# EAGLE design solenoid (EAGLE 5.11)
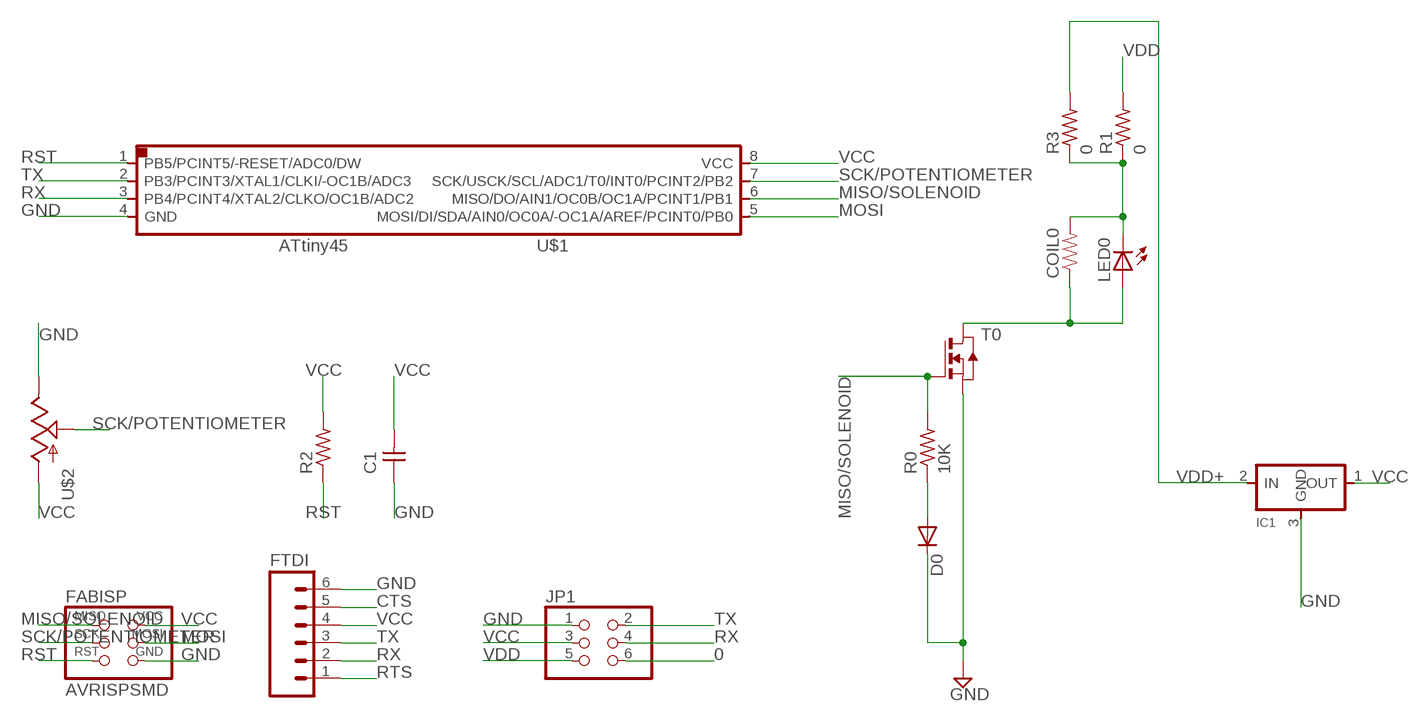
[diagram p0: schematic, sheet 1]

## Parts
C1  UNPOLARIZED_CAPACITOR1206  [1206]
COIL0  RESISTOR1206  [1206]
D0  DIODESOD123  [SOD123]
FABISP  AVRISPSMD  [2X03SMD]
FTDI  M06SMD  [1X06-SMD]
IC1  REGULATORSOT23  [SOT23]
JP1  PINHD-2X3-SMD  [2X03SMD]
LED0  LED1206  [1206]
R0  10K  RESISTOR1206  [1206]
R1  0  RESISTOR1206  [1206]
R2  RESISTOR1206  [1206]
R3  0  RESISTOR1206  [1206]
T0  NMOSFETSOT23  [SOT-23]
U$1  ATTINY45SI  [SOIC8]
U$2  POT  [ALPS_POT]

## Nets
0: JP1.6
CO0: COIL0.1 LED0.1(A) T0.1(D)
CTS: FTDI.5
GND: C1.1 D0.CATHODE(C) FABISP.6(GND) FTDI.6 IC1.3(GND) JP1.1 T0.2(S) U$1.4(GND) U$2.P$1(E)
MISO/SOLENOID: FABISP.1(MISO) R0.2 T0.3(G) U$1.6(MISO/DO/AIN1/OC0B/OC1A/PCINT1/PB1)
MOSI: FABISP.4(MOSI) U$1.5(MOSI/DI/SDA/AIN0/OC0A/-OC1A/AREF/PCINT0/PB0)
N$1: COIL0.2 LED0.2(C) R1.1 R3.1
R0: D0.ANODE(A) R0.1
RST: FABISP.5(RST) R2.1 U$1.1(PB5/PCINT5/-RESET/ADC0/DW)
RTS: FTDI.1
RX: FTDI.2 JP1.4 U$1.3(PB4/PCINT4/XTAL2/CLKO/OC1B/ADC2)
SCK/POTENTIOMETER: FABISP.3(SCK) U$1.7(SCK/USCK/SCL/ADC1/T0/INT0/PCINT2/PB2) U$2.P$2(S)
TX: FTDI.3 JP1.2 U$1.2(PB3/PCINT3/XTAL1/CLKI/-OC1B/ADC3)
VCC: C1.2 FABISP.2(VCC) FTDI.4 IC1.1(OUT) JP1.3 R2.2 U$1.8(VCC) U$2.P$3(A)
VDD: JP1.5 R1.2
VDD+: IC1.2(IN) R3.2

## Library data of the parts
C1 = ng:UNPOLARIZED_CAPACITOR: unpolarized_capacitor
COIL0 = SparkFun:RESISTOR: Resistor
D0 = ng:DIODE: DIODE
FABISP = fab:AVRISP
FTDI = SparkFun:M06: Header 6 Standard 6-pin 0.1" header. Use with straight break away headers (SKU : PRT-00116), right angle break away headers (PRT-00553), swiss pins (PRT-00743), machine pins (PRT-00117), and female headers (PRT-00115). Molex polarized connector foot print use with SKU : PRT-08094 with associated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
IC1 = ng:REGULATOR
JP1 = fab:PINHD-2X3-SMD: PIN HEADER
LED0 = ng:LED
R0 R1-R3 = ng:RESISTOR
T0 = ng:NMOSFET: MOS FET
U$1 = fab:ATTINY45
U$2 = SparkFun:POT

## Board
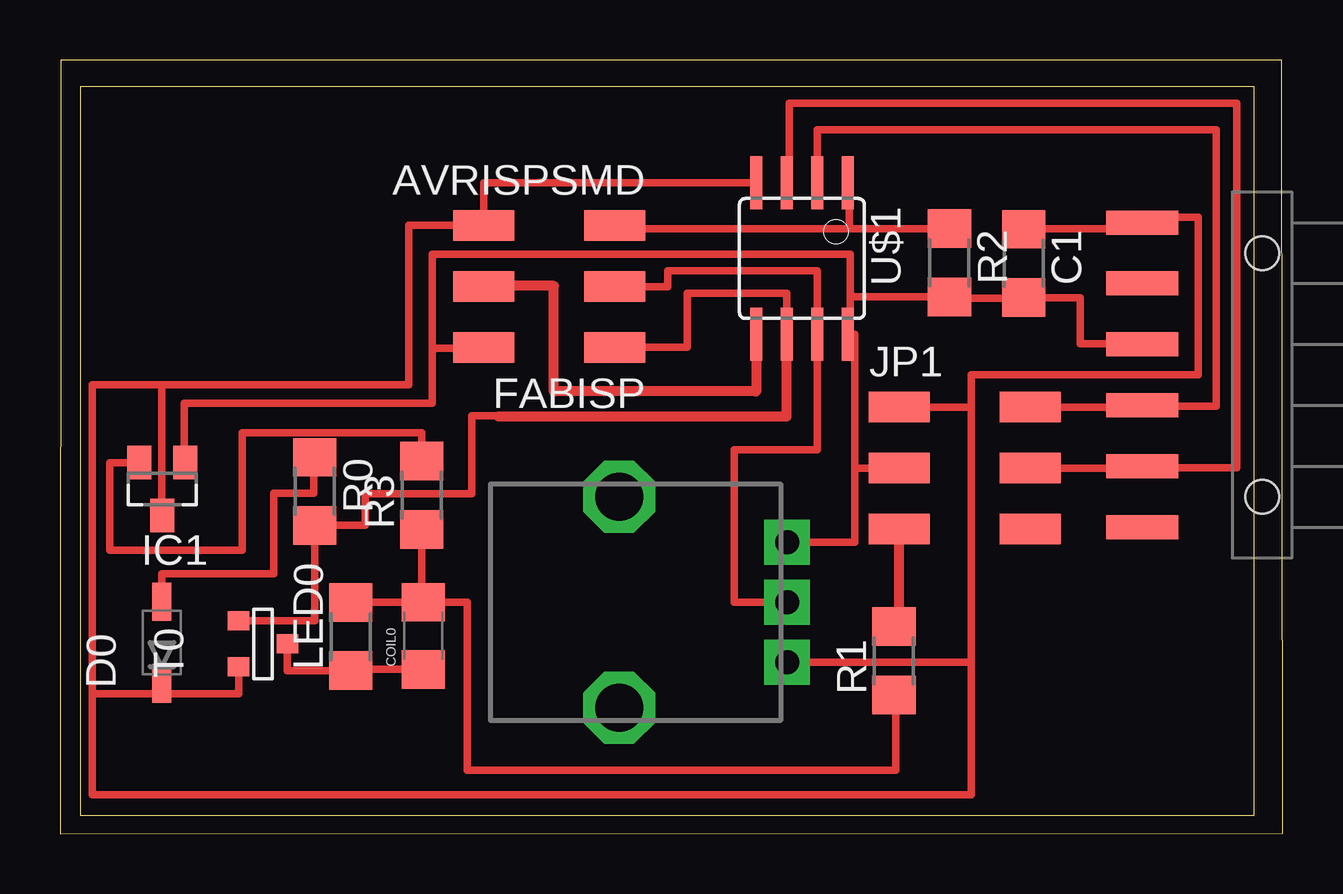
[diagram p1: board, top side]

Size 50.95 x 32.25 mm. Coordinates in mm from the lower left corner, seen from the top.
Outline: 0,0 50.95,0.03 50.9,32.25 0.03,32.25 0,0
Copper layers (1*16): Top 0.035mm / dielectric 1.5mm / Bottom 0.035mm
Design rules "default": minimum track width 10mil, minimum drill 24mil, track to track 8mil, track to pad 8mil, pad to pad 8mil, via to via 8mil, smd to smd 8mil, copper to edge 40mil, drill to drill 8mil, minimum pad ring 10mil, minimum via ring 8mil, stop-mask expansion 4mil, vias tented up to drill 0mil, thermal gap 10mil
Milling: area 0.8,0.8 to 49.8,31.1

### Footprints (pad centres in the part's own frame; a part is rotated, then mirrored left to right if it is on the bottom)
1206 = smd 1.6 x 1.803: 1 -1.422,0; 2 1.422,0
1206' = smd 1.6 x 1.8: 1 -1.4,0; 2 1.4,0
SOD123 = smd 1.6 x 0.8: ANODE 1.7,0; CATHODE -1.7,0
2X03SMD = smd 2.54 x 1.27: 1 -2.54,2.54; 2 2.92,2.54; 3 -2.54,0; 4 2.92,0; 5 -2.54,-2.54; 6 2.92,-2.54
1X06-SMD = smd 1 x 3: 1 -6.35,5; 2 -3.81,5; 3 -1.27,5; 4 1.27,5; 5 3.81,5; 6 6.35,5 | hole 1.4: -5.08,0; 5.08,0
SOT23 = smd 1 x 1.4: 1 -0.95,-1.1; 2 0.95,-1.1; 3 0,1.1
SOT-23 = smd 0.787 x 0.889: 1 0.025,-1.016; 2 -0.94,1.016; 3 0.991,1.016
SOIC8 = smd 0.5 x 2.2: 1 -1.905,-3.154; 2 -0.645,-3.154; 3 0.625,-3.154; 4 1.895,-3.154; 5 1.905,3.154; 6 0.635,3.154; 7 -0.635,3.154; 8 -1.905,3.154
ALPS_POT = drill 1 pad 1.88 square: P$1 7,-2.5; P$2 7,0; P$3 7,2.5 | drill 2 octagon: P$4 0,-4.4; P$5 0,4.4

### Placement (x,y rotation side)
C1  40.16,23.77 270 top
COIL0  [1206']  15.14,8.26 90 top
D0  4.24,7.98 90 top
FABISP  20.57,22.81 180 top
FTDI  50.09,19.13 90 top
IC1  4.26,14.37 180 top
JP1  37.52,15.24 0 top
LED0  12.12,8.23 90 top
R0  10.62,14.27 270 top
R1  34.75,7.21 90 top
R2  37.06,23.8 270 top
R3  15.07,14.11 90 top
T0  8.46,7.9 90 top
U$1  30.91,23.98 180 top
U$2  23.29,9.65 0 top

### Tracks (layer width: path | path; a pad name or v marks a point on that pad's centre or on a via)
CO0
  Top 0.305: COIL0.1 12.12,6.86 LED0.1 9.47,6.81 T0.1
GND
  Top 0.305: C1.1 40.21,25.2 40.21,25.22 45.09,25.22 FTDI.6 45.09,25.7 47.42,25.7 47.42,19.13 37.97,19.13 37.97,17.78 | U$1.4 17.65,27.13 FABISP.6 | FABISP.6 17.65,25.32 | 7.52,6.96 T0.2 7.44,5.84 4.24,5.84 | 4.24,5.84 D0.CATHODE | 1.35,5.84 1.35,1.63 37.97,1.63 37.97,7.15 | 37.97,7.15 U$2.P$1 | 37.97,17.78 JP1.1 | 37.97,7.15 37.97,17.78 | 1.35,5.84 4.24,5.84 | 1.35,5.84 1.35,18.73 4.24,18.73 | 4.24,18.73 14.54,18.73 14.54,25.37 17.65,25.37 FABISP.6 | IC1.3 4.24,13.27 4.24,18.73
MISO/SOLENOID
  Top 0.305: FABISP.1 26.14,20.27 26.14,22.53 30.28,22.53 U$1.6 | T0.3 10.62,8.89 R0.2 12.72,12.85 12.72,14.17 17.16,14.17 17.16,17.42 18.28,17.42 18.28,17.4
  Top 0.406: 18.28,17.4 30.28,17.4 U$1.6
MOSI
  Top 0.406: U$1.5 29.01,18.44 20.57,18.44 20.57,22.84 17.65,22.84 FABISP.4
N$1
  Top 0.305: R1.1 34.82,5.79 34.82,2.66 16.97,2.66 16.97,9.65 COIL0.2 | COIL0.2 | COIL0.2 LED0.2 | COIL0.2 15.07,9.65 | COIL0.2 15.07,9.65 | 15.07,9.65 R3.1
R0
  Top 0.305: R0.1 10.62,15.72 10.57,15.72 10.57,14.21 8.91,14.21 8.91,10.85 4.24,10.85 D0.ANODE
RST
  Top 0.305: 32.89,25.22 23.11,25.22 FABISP.5 | 32.89,25.22 R2.1 | U$1.1 32.89,27.13 32.89,25.22
RX
  Top 0.305: U$1.3 30.38,27.13 30.38,30.45 49.02,30.45 49.02,15.27 45.62,15.27 | 45.62,15.27 45.09,15.27 FTDI.2 | JP1.4 45.62,15.24 45.62,15.27
SCK/POTENTIOMETER
  Top 0.305: FABISP.3 25.32,22.81 25.32,23.47 31.55,23.47 U$1.7 31.55,16 28.09,16 28.09,9.65 U$2.P$2
TX
  Top 0.305: U$1.2 31.55,27.13 31.55,29.34 48.18,29.34 48.18,17.83 45.67,17.83 | 45.67,17.83 45.09,17.83 FTDI.3 | JP1.2 45.67,17.78 45.67,17.83
VCC
  Top 0.305: 32.92,20.82 U$1.8 | 32.92,22.38 32.92,24.16 15.52,24.16 15.52,20.24 | FABISP.2 17.65,20.24 15.52,20.24 | 32.92,22.38 R2.2 37.11,22.38 37.11,22.33 40.16,22.33 C1.2 40.23,22.35 | 32.92,22.38 32.92,20.82 | 40.23,22.35 | 40.23,22.35 42.52,22.35 42.52,20.42 45.09,20.42 FTDI.4 | 32.92,20.82 33.12,20.82 33.12,15.24 | 33.12,15.24 JP1.3 | U$2.P$3 33.12,12.15 33.12,15.24 | IC1.1 5.17,15.47 5.17,17.95 15.52,17.95 15.52,20.24
VDD
  Top 0.406: R1.2 34.98,8.64 JP1.5
VDD+
  Top 0.305: IC1.2 2.08,15.47 2.08,11.81 7.6,11.81 7.6,16.72 15.07,16.72 R3.2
